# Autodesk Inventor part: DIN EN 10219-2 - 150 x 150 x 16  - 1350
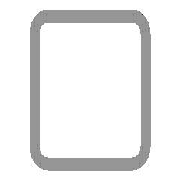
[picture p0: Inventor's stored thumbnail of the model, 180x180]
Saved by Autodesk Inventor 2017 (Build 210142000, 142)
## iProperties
_CCFamilyMember: 76
_CCFamilyDisplayName: DIN EN 10219-2 (Square Hollow Section - Cold Formed) - Cold formed welded structural hollow sections of non-alloy and fine grain structural steel
_FrameMemberDoc: Frame Member File
_Version: 15.0.0
_GetPNFromCC: 1
Created: 2016-02
Part Number: DIN EN 10219-2 - 150 x 150 x 16  - 1350
Material: Steel, Mild
Description: Cold formed welded structural hollow sections of non-alloy and fine grain structural steel
Document SubType Name: Modeling
Standard: DIN
Designer: iusti
Standard Revision: 2006-07
Standards Organization: DIN
Language: en-US
Size Designation: 150 x 150 x 16
Categories: <MemberInstance><Categories><Category DisplayName="Structural Shapes" InternalName="089c4875-fa83-4c05-b084-43b9cc11f5ed" Mnemonic="GRDR"><CategoryParameter Dis
Stock Number: 150 x 150 x 16
Mass: 79240 g
Surface Area: 12767.4 cm^2
Volume: 10094.3 cm^3
Density: 7.85 g/cm^3
Appearance: Semi-Polished
IsCustomPart: 1
G_L: 1350.000 mm
G_W: 150.000 mm
G_H: 150.000 mm
+CEF86B8C-3238-420E-ADC4-8D9549012C8A+CUTDETAIL1: Cut
+AF8588F7-3CA6-436D-9A69-B39F8946184A+CUTDETAIL2: Cut
Author: iusti
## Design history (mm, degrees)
node "Start plane"
node "End plane"
sketch "Sketch"
  geometry: L1 (-75, -27)-(-75, 27); L2 (-27, 75)-(27, 75); L3 (75, 27)-(75, -27); L4 (27, -75)-(-27, -75); L5 (-27, 59)-(27, 59); L6 (59, 27)-(59, -27); L7 (27, -59)-(-27, -59); L8 (-59, -27)-(-59, 27); L9 (0, 118.918)-(0, -118.918) reference; L10 (-118.918, 0)-(118.918, 0) reference; A1 r 48 centre (-27, -27) between (-75, -27) and (-27, -75); A2 r 48 centre (-27, 27) between (-27, 75) and (-75, 27); A3 r 48 centre (27, 27) between (75, 27) and (27, 75); A4 r 48 centre (27, -27) between (27, -75) and (75, -27); A5 r 32 centre (-27, 27) between (-27, 59) and (-59, 27); A6 r 32 centre (27, 27) between (59, 27) and (27, 59); A7 r 32 centre (27, -27) between (27, -59) and (59, -27); A8 r 32 centre (-27, -27) between (-59, -27) and (-27, -59)
  constraints: 16 end point, 16 point on circle, 8 centre point, 8 tangent, 4 parallel, 3 equal radius, 2 perpendicular, 7 other
  dimensions: "d7" = 48 radius of A1 (= G_IR); "d10" = 150 distance between parallel lines of L2 L4 (= G_H); "d11" = 150 distance between parallel lines of L1 L3 (= G_W); "d12" = 16 distance between parallel lines of L3 L6 (= G_T); "d15" = 75 distance between parallel lines of L2 L10 (= 0.5 x d10); "d16" = 75 distance between parallel lines of L9 L3 (= 0.5 x d11)
extrude "Body" new body sketch "Sketch" stored distance "d3" = 1350 (= G_L); taper "d4" = 0 deg
node "Driven Length"
  sketch "Sketch3"
    geometry: L1 (0, 0)-(10, 0) reference
    constraints: 2 end point, 1 horizontal
  workplane "Work Plane3"
  sketch "Sketch4"
    geometry: L1 (-2, 75)-(12, 75) reference; L2 (-2, 1425)-(12, 1425) reference
    dimensions: "d18" = 1350 distance between parallel lines of L1 L2 (derived)
workplane "Work Plane4"
split "Split1"
workplane "Work Plane5"
split "Split2"
body "Solid1"
other parameters: "G_W" = 150 [user parameter; used in 1 equation term], "G_H" = 150 [user parameter; used in 1 equation term], "G_T" = 16 [user parameter; used in 1 equation term], "G_IR" = 48 [user parameter; used in 1 equation term], "G_L" = 1350 (= d18) [user parameter; used in 1 equation term], "G_OFFSET_START" = -75 [user parameter; used in 1 equation term], "G_OFFSET_END" = -75 [user parameter; used in 1 equation term], "d13" = 75 (= -G_OFFSET_START), "d14" = 1425 (= G_OFFSET_END + B_L), "d17" = 90 deg
